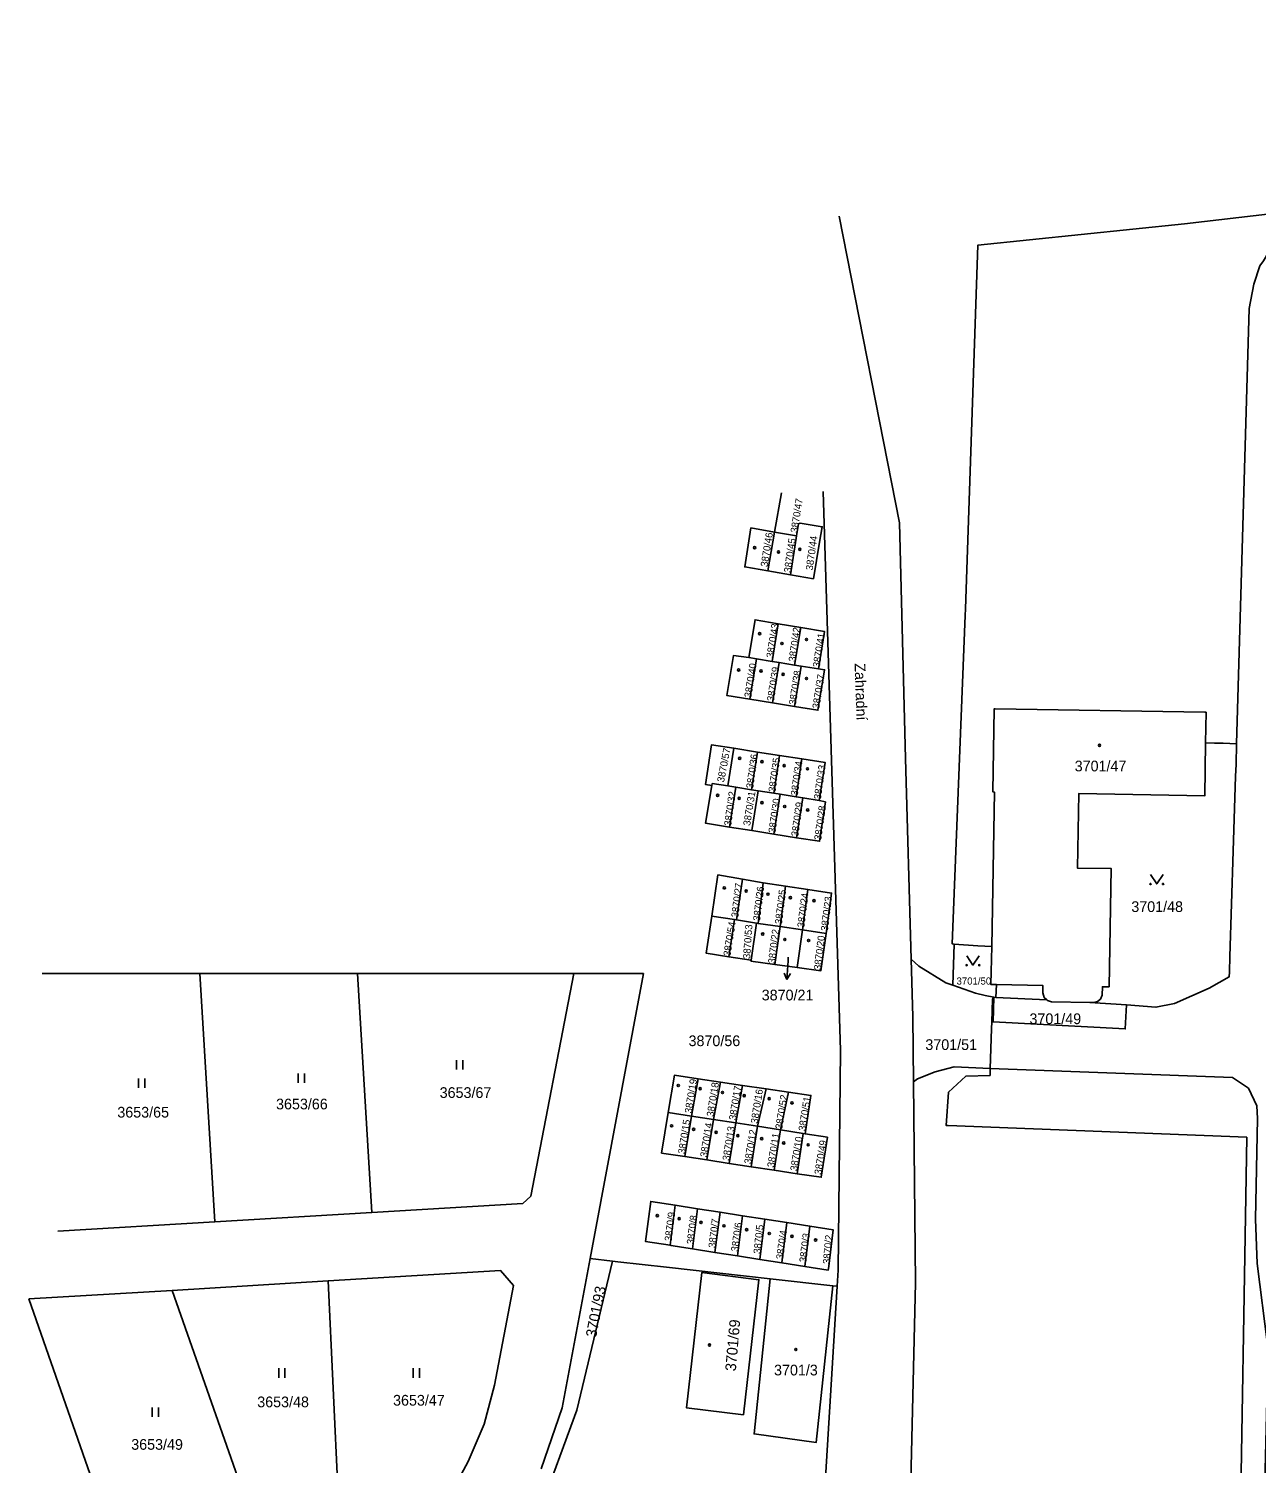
# Model space of a CAD drawing. Extents: x -527335 to -526256, y -1079142 to -1077809.
# Drawn here: x -527287.8 to -527092.7, y -1078063.8 to -1077835.8 of the extents above; entities that cross this region are included whole.
import ezdxf

# ---------------------------------------------------------------- set-up
doc = ezdxf.new("R2010")
doc.units = 0
for name, color, linetype in [('Vrstva 1', 7, 'Continuous'), ('Vrstva 2', 7, 'Continuous'), ('Vrstva 3', 7, 'Continuous'), ('Vrstva 4', 7, 'Continuous'), ('Vrstva 5', 7, 'Continuous'), ('Vrstva 7', 7, 'Continuous')]:
    doc.layers.add(name, color=color, linetype=linetype)

msp = doc.modelspace()

# ---------------------------------------------------------------- linework, layer by layer
at = {"layer": 'Vrstva 1'}
for p, q in [((-527168.2, -1077909.59), (-527169.28, -1077915.83)), ((-527169.28, -1077915.83), (-527173.06, -1077915.17)), ((-527169.28, -1077915.83), (-527170.35, -1077921.99)), ((-527165.79, -1077916.44), (-527169.28, -1077915.83)), ((-527170.35, -1077921.99), (-527166.78, -1077922.61)), ((-527168.69, -1077930.38), (-527169.69, -1077936.37)), ((-527165.12, -1077930.97), (-527168.69, -1077930.38)), ((-527165.12, -1077930.97), (-527166.12, -1077936.96)), ((-527172.16, -1077935.97), (-527173.38, -1077935.77)), ((-527172.16, -1077935.97), (-527173.2, -1077942.38)), ((-527169.69, -1077936.37), (-527172.16, -1077935.97)), ((-527168.57, -1077936.56), (-527169.69, -1077936.37)), ((-527168.57, -1077936.56), (-527169.61, -1077942.96)), ((-527166.12, -1077936.96), (-527168.57, -1077936.56)), ((-527165.08, -1077937.13), (-527166.12, -1077936.96)), ((-527165.08, -1077937.13), (-527166.12, -1077943.53)), ((-527162.33, -1077937.58), (-527165.08, -1077937.13)), ((-527173.2, -1077942.38), (-527169.61, -1077942.96)), ((-527169.61, -1077942.96), (-527166.12, -1077943.53)), ((-527175.75, -1077950.19), (-527176.69, -1077956.16)), ((-527172, -1077950.78), (-527175.75, -1077950.19)), ((-527172, -1077950.78), (-527172.94, -1077956.76)), ((-527168.48, -1077951.33), (-527172, -1077950.78)), ((-527168.48, -1077951.33), (-527169.41, -1077957.33)), ((-527164.93, -1077951.88), (-527168.48, -1077951.33)), ((-527164.93, -1077951.88), (-527165.87, -1077957.9)), ((-527175.46, -1077956.36), (-527176.69, -1077956.16)), ((-527175.46, -1077956.36), (-527176.46, -1077962.7)), ((-527172.94, -1077956.76), (-527175.46, -1077956.36)), ((-527171.91, -1077956.93), (-527172.94, -1077956.76)), ((-527171.91, -1077956.93), (-527172.91, -1077963.26)), ((-527169.41, -1077957.33), (-527171.91, -1077956.93)), ((-527168.41, -1077957.49), (-527169.41, -1077957.33)), ((-527168.41, -1077957.49), (-527169.41, -1077963.82)), ((-527165.87, -1077957.9), (-527168.41, -1077957.49)), ((-527164.78, -1077958.07), (-527165.87, -1077957.9)), ((-527164.78, -1077958.07), (-527165.78, -1077964.39)), ((-527162.18, -1077958.49), (-527164.78, -1077958.07)), ((-527176.46, -1077962.7), (-527172.91, -1077963.26)), ((-527172.91, -1077963.26), (-527169.41, -1077963.82)), ((-527169.41, -1077963.82), (-527165.78, -1077964.39)), ((-527174.41, -1077971), (-527175.35, -1077977.47)), ((-527171.1, -1077971.58), (-527174.41, -1077971)), ((-527171.1, -1077971.58), (-527171.88, -1077978.01)), ((-527167.53, -1077972.11), (-527171.1, -1077971.58)), ((-527167.53, -1077972.11), (-527168.41, -1077978.53)), ((-527163.98, -1077972.63), (-527167.53, -1077972.11)), ((-527163.98, -1077972.63), (-527164.85, -1077979.06)), ((-527179.26, -1077976.86), (-527175.68, -1077977.42)), ((-527175.68, -1077977.42), (-527176.58, -1077983.31)), ((-527175.68, -1077977.42), (-527175.35, -1077977.47)), ((-527175.35, -1077977.47), (-527172.18, -1077977.97)), ((-527172.18, -1077977.97), (-527173.01, -1077983.85)), ((-527171.88, -1077978.01), (-527172.18, -1077977.97)), ((-527168.41, -1077978.53), (-527171.88, -1077978.01)), ((-527168.41, -1077978.53), (-527169.23, -1077984.55)), ((-527164.85, -1077979.06), (-527168.41, -1077978.53)), ((-527164.85, -1077979.06), (-527165.67, -1077985.04)), ((-527161.11, -1077979.61), (-527164.85, -1077979.06)), ((-527140.94, -1077987.84), (-527140.72, -1077981.29)), ((-527176.58, -1077983.31), (-527173.01, -1077983.85)), ((-527285.69, -1077985.99), (-527260.64, -1077985.98)), ((-527260.64, -1077985.98), (-527235.6, -1077985.97)), ((-527258.27, -1078025.45), (-527260.64, -1077985.98)), ((-527235.6, -1077985.97), (-527201.2, -1077985.95)), ((-527233.32, -1078023.96), (-527235.6, -1077985.97)), ((-527201.2, -1077985.95), (-527208.02, -1078021.38)), ((-527201.2, -1077985.95), (-527190.13, -1077985.95)), ((-527190.13, -1077985.95), (-527198.62, -1078031.28)), ((-527169.23, -1077984.55), (-527165.67, -1077985.04)), ((-527119.18, -1077990.58), (-527113.33, -1077990.97)), ((-527181.44, -1078002.7), (-527182.49, -1078008.63)), ((-527177.88, -1078003.23), (-527181.44, -1078002.7)), ((-527177.88, -1078003.23), (-527179, -1078009.17)), ((-527174.36, -1078003.75), (-527177.88, -1078003.23)), ((-527174.36, -1078003.75), (-527175.45, -1078009.72)), ((-527170.64, -1078004.32), (-527174.36, -1078003.75)), ((-527172, -1078010.26), (-527170.64, -1078004.32)), ((-527167.08, -1078004.82), (-527170.64, -1078004.32)), ((-527167.08, -1078004.82), (-527168.36, -1078010.83)), ((-527182.49, -1078008.63), (-527186.19, -1078008.06)), ((-527182.49, -1078008.63), (-527183.55, -1078015.08)), ((-527179, -1078009.17), (-527182.49, -1078008.63)), ((-527179, -1078009.17), (-527180.04, -1078015.61)), ((-527175.45, -1078009.72), (-527179, -1078009.17)), ((-527175.45, -1078009.72), (-527176.48, -1078016.15)), ((-527172, -1078010.26), (-527175.45, -1078009.72)), ((-527172, -1078010.26), (-527173.03, -1078016.68)), ((-527168.36, -1078010.83), (-527172, -1078010.26)), ((-527168.36, -1078010.83), (-527169.37, -1078017.23)), ((-527164.72, -1078011.39), (-527168.36, -1078010.83)), ((-527165.72, -1078017.79), (-527164.72, -1078011.39)), ((-527164.4, -1078011.44), (-527164.72, -1078011.39)), ((-527183.55, -1078015.08), (-527180.04, -1078015.61)), ((-527180.04, -1078015.61), (-527176.48, -1078016.15)), ((-527176.48, -1078016.15), (-527173.03, -1078016.68)), ((-527173.03, -1078016.68), (-527169.37, -1078017.23)), ((-527169.37, -1078017.23), (-527165.72, -1078017.79)), ((-527233.32, -1078023.96), (-527258.27, -1078025.45)), ((-527185.08, -1078022.81), (-527185.88, -1078029.17)), ((-527181.52, -1078023.36), (-527185.08, -1078022.81)), ((-527181.52, -1078023.36), (-527182.33, -1078029.74)), ((-527177.96, -1078023.92), (-527181.52, -1078023.36)), ((-527177.96, -1078023.92), (-527178.77, -1078030.3)), ((-527174.39, -1078024.47), (-527177.96, -1078023.92)), ((-527174.39, -1078024.47), (-527175.2, -1078030.87)), ((-527170.84, -1078025.02), (-527174.39, -1078024.47)), ((-527170.84, -1078025.02), (-527171.65, -1078031.43)), ((-527167.33, -1078025.57), (-527170.84, -1078025.02)), ((-527258.27, -1078025.45), (-527283.23, -1078026.95)), ((-527167.33, -1078025.57), (-527168.15, -1078031.98)), ((-527163.67, -1078026.14), (-527167.33, -1078025.57)), ((-527163.67, -1078026.14), (-527164.48, -1078032.56)), ((-527198.62, -1078031.28), (-527195.06, -1078031.68)), ((-527182.33, -1078029.74), (-527178.77, -1078030.3)), ((-527178.77, -1078030.3), (-527175.2, -1078030.87)), ((-527175.2, -1078030.87), (-527171.65, -1078031.43)), ((-527171.65, -1078031.43), (-527168.15, -1078031.98)), ((-527168.15, -1078031.98), (-527164.48, -1078032.56)), ((-527287.85, -1078037.7), (-527265.02, -1078036.33)), ((-527265.02, -1078036.33), (-527240.25, -1078034.84)), ((-527265.02, -1078036.33), (-527249.76, -1078079.88)), ((-527240.25, -1078034.84), (-527238.34, -1078075.88)), ((-527160.02, -1078035.61), (-527169.98, -1078034.5)), ((-527159.33, -1078035.65), (-527160.02, -1078035.61)), ((-527287.85, -1078037.7), (-527270.53, -1078087.15))]:
    msp.add_line(p, q, dxfattribs=at)
for points in [[(-527140.72, -1077981.29), (-527141.06, -1077981.26), (-527138.97, -1077929.07), (-527138.93, -1077928.01), (-527137, -1077870.25), (-527104.11, -1077866.84), (-527021.38, -1077857.18), (-526949.01, -1077848.73), (-526843.67, -1077835.82)], [(-527095.85, -1077949.48), (-527093.83, -1077880.31), (-527093.1, -1077876.42), (-527092.14, -1077873.52), (-527091.56, -1077872.71), (-527090.02, -1077870.13), (-527087.99, -1077867.99), (-527085.4, -1077866.41), (-527080.52, -1077865.39), (-527007.85, -1077858.12), (-527005.84, -1077858.19), (-527004.97, -1077858.67), (-527002.17, -1077860.18), (-526999.36, -1077862.55), (-526998.01, -1077864.28), (-526997.69, -1077865.73), (-526997.86, -1077871.23)], [(-527147.58, -1077983.71), (-527148.5, -1077951.81), (-527149.41, -1077914.37), (-527159.03, -1077865.64)], [(-527161.57, -1077909.37), (-527158.79, -1077998.21), (-527159.18, -1078033.14), (-527159.33, -1078035.65)], [(-527173.06, -1077915.17), (-527174.03, -1077921.36), (-527170.35, -1077921.99)], [(-527166.78, -1077922.61), (-527163.1, -1077923.24), (-527162.13, -1077917.42), (-527161.72, -1077914.97), (-527165.2, -1077914.39)], [(-527165.2, -1077914.39), (-527165.48, -1077914.49), (-527165.79, -1077916.44)], [(-527165.79, -1077916.44), (-527165.85, -1077916.79), (-527166.78, -1077922.61)], [(-527168.69, -1077930.38), (-527172.38, -1077929.76), (-527173.38, -1077935.77)], [(-527162.33, -1077937.58), (-527161.37, -1077931.6), (-527165.12, -1077930.97)], [(-527173.38, -1077935.77), (-527175.8, -1077935.42), (-527176.88, -1077941.78), (-527173.2, -1077942.38)], [(-527166.12, -1077943.53), (-527162.39, -1077944.13), (-527161.35, -1077937.71), (-527162.33, -1077937.58)], [(-527134.77, -1077981.69), (-527134.33, -1077957.14), (-527134.59, -1077957.12), (-527134.36, -1077943.9), (-527134.2, -1077943.9), (-527100.92, -1077944.46), (-527100.7, -1077944.46), (-527100.77, -1077949.3)], [(-527179.25, -1077956.09), (-527180.29, -1077955.93), (-527179.29, -1077949.62), (-527175.75, -1077950.19)], [(-527119.18, -1077990.58), (-527118.6, -1077990.59), (-527117.95, -1077990.44), (-527117.46, -1077990.03), (-527117.21, -1077989.41), (-527117.18, -1077988.07), (-527116.12, -1077988.08), (-527115.76, -1077969.29), (-527121.12, -1077969.24), (-527120.93, -1077957.39), (-527100.9, -1077957.75), (-527100.77, -1077949.3)], [(-527095.85, -1077949.48), (-527095.91, -1077952.75), (-527096.01, -1077954.59), (-527096.41, -1077966.53), (-527096.91, -1077983.27), (-527096.98, -1077985.7), (-527097.03, -1077986.51), (-527100.23, -1077988.31), (-527105.72, -1077990.75), (-527108.68, -1077991.35), (-527113.33, -1077990.97)], [(-527100.77, -1077949.3), (-527099.35, -1077949.35), (-527097.98, -1077949.39), (-527095.85, -1077949.48)], [(-527162.18, -1077958.49), (-527161.24, -1077952.46), (-527164.93, -1077951.88)], [(-527179.25, -1077956.09), (-527180.24, -1077962.1), (-527176.46, -1077962.7)], [(-527176.69, -1077956.16), (-527179.2, -1077955.79), (-527179.25, -1077956.09)], [(-527165.78, -1077964.39), (-527162.13, -1077964.97), (-527161.21, -1077958.7), (-527162.18, -1077958.49)], [(-527174.41, -1077971), (-527178.3, -1077970.31), (-527179.26, -1077976.86)], [(-527161.11, -1077979.61), (-527160.23, -1077973.19), (-527163.98, -1077972.63)], [(-527179.26, -1077976.86), (-527180.14, -1077982.77), (-527176.58, -1077983.31)], [(-527165.67, -1077985.04), (-527161.93, -1077985.54), (-527161.11, -1077979.61)], [(-527140.72, -1077981.29), (-527137, -1077981.57), (-527134.77, -1077981.69)], [(-527134.77, -1077981.69), (-527134.89, -1077987.73), (-527134.03, -1077987.75)], [(-527173.01, -1077983.85), (-527173.04, -1077984.04), (-527169.23, -1077984.55)], [(-527147.58, -1077983.71), (-527146.35, -1077984.82), (-527142.07, -1077987.45), (-527140.94, -1077987.84)], [(-527147.21, -1078003.19), (-527147.31, -1077992.85), (-527147.58, -1077983.71)], [(-527140.94, -1077987.84), (-527137.35, -1077989.08), (-527135.82, -1077989.47), (-527134.43, -1077989.76)], [(-527134.03, -1077987.75), (-527134.13, -1077989.77), (-527134.43, -1077989.76)], [(-527134.03, -1077987.75), (-527126.63, -1077987.9), (-527126.65, -1077989.07), (-527126.44, -1077989.79), (-527126.03, -1077990.18), (-527125.92, -1077990.28), (-527125.26, -1077990.48), (-527119.18, -1077990.58)], [(-527134.43, -1077989.76), (-527134.66, -1077990.04), (-527134.76, -1077993.65), (-527134.79, -1077994.78), (-527135, -1078001.05)], [(-527113.33, -1077990.97), (-527113.55, -1077994.78), (-527134.55, -1077993.66), (-527134.43, -1077989.76)], [(-527181.44, -1078002.7), (-527185.21, -1078002.14), (-527186.19, -1078008.06)], [(-527147.21, -1078003.19), (-527146.56, -1078002.73), (-527143.75, -1078001.6), (-527140.75, -1078000.83), (-527135, -1078001.05)], [(-527135, -1078001.05), (-527135.04, -1078002.18), (-527138.91, -1078002.31), (-527141.63, -1078004.83), (-527142.01, -1078010.14), (-527141.69, -1078010.15), (-527094.23, -1078012.01), (-527095.45, -1078084.25), (-527022.3, -1078086.11), (-527016.88, -1078088.83)], [(-527015.84, -1078035.65), (-527015.24, -1078041.58), (-527017.7, -1078076.04), (-527091.49, -1078073.63), (-527090.95, -1078049.51), (-527090.94, -1078045), (-527092.6, -1078032.05), (-527092.82, -1078025.03), (-527092.53, -1078009.03), (-527092.64, -1078007.02), (-527093.93, -1078004.22), (-527096.47, -1078002.52), (-527135, -1078001.05)], [(-527151.32, -1078203.19), (-527149.15, -1078119.04), (-527147.89, -1078077.9), (-527146.9, -1078035.16), (-527147.21, -1078003.19)], [(-527164.4, -1078011.44), (-527163.51, -1078005.35), (-527167.08, -1078004.82)], [(-527186.19, -1078008.06), (-527187.25, -1078014.51), (-527183.55, -1078015.08)], [(-527165.72, -1078017.79), (-527161.87, -1078018.37), (-527160.88, -1078011.99), (-527164.4, -1078011.44)], [(-527208.02, -1078021.38), (-527209.32, -1078022.52), (-527233.32, -1078023.96)], [(-527185.08, -1078022.81), (-527188.98, -1078022.2), (-527189.82, -1078028.55), (-527185.88, -1078029.17)], [(-527164.48, -1078032.56), (-527160.77, -1078033.15), (-527160.74, -1078032.91), (-527159.95, -1078026.72), (-527163.67, -1078026.14)], [(-527185.88, -1078029.17), (-527185.7, -1078029.2), (-527184.06, -1078029.46), (-527182.33, -1078029.74)], [(-527195.06, -1078031.68), (-527200.73, -1078055.36), (-527206.71, -1078071.69), (-527212.24, -1078081.56)], [(-527198.62, -1078031.28), (-527203.07, -1078055.03), (-527206.41, -1078064.7)], [(-527169.98, -1078034.5), (-527186.45, -1078032.65), (-527194.19, -1078031.78), (-527195.06, -1078031.68)], [(-527240.25, -1078034.84), (-527212.84, -1078033.2), (-527210.76, -1078035.57), (-527213.81, -1078051.42), (-527215.47, -1078057.62), (-527217.99, -1078063.51), (-527221.44, -1078069.96)], [(-527174.21, -1078056.09), (-527183.27, -1078055.01), (-527180.87, -1078033.51), (-527171.77, -1078034.65), (-527174.21, -1078056.09)], [(-527160.02, -1078035.61), (-527162.69, -1078060.52), (-527172.55, -1078059.14), (-527169.98, -1078034.5)], [(-527168.74, -1078213.47), (-527166.4, -1078148.92), (-527166.12, -1078143.69), (-527163.93, -1078111.36), (-527159.33, -1078035.65)]]:
    msp.add_lwpolyline(points, dxfattribs=at)
at = {"layer": 'Vrstva 3'}
for p, q in [((-527219.85, -1078001.23), (-527219.85, -1077999.73)), ((-527218.85, -1078001.23), (-527218.85, -1077999.73)), ((-527245, -1078003.35), (-527245, -1078001.85)), ((-527244, -1078003.35), (-527244, -1078001.85)), ((-527270.41, -1078004.15), (-527270.41, -1078002.65)), ((-527269.41, -1078004.15), (-527269.41, -1078002.65)), ((-527248.11, -1078050.21), (-527248.11, -1078048.71)), ((-527247.11, -1078050.21), (-527247.11, -1078048.71)), ((-527226.73, -1078050.21), (-527226.73, -1078048.71)), ((-527225.73, -1078050.21), (-527225.73, -1078048.71)), ((-527268.23, -1078056.43), (-527268.23, -1078054.93)), ((-527267.23, -1078056.43), (-527267.23, -1078054.93))]:
    msp.add_line(p, q, dxfattribs=at)
for points in [[(-527109.53, -1077970.25), (-527108.53, -1077971.75), (-527107.53, -1077970.25)], [(-527138.75, -1077983.15), (-527137.75, -1077984.65), (-527136.75, -1077983.15)]]:
    msp.add_lwpolyline(points, dxfattribs=at)
for centre in [(-527109.53, -1077971.75), (-527107.53, -1077971.75), (-527138.75, -1077984.65), (-527136.75, -1077984.65)]:
    msp.add_circle(centre, 0.1, dxfattribs=at)
at = {"layer": 'Vrstva 4'}
for p, q in [((-527126.03, -1077990.18), (-527134.13, -1077989.77)), ((-527134.55, -1077993.66), (-527134.76, -1077993.65))]:
    msp.add_line(p, q, dxfattribs=at)
at = {"layer": 'Vrstva 5'}
for centre in [(-527172.46, -1077918.3), (-527168.66, -1077918.98), (-527165.27, -1077918.56), (-527171.66, -1077931.96), (-527168.11, -1077933.53), (-527164.21, -1077932.9), (-527175, -1077937.74), (-527171.43, -1077937.9), (-527167.93, -1077938.44), (-527164.21, -1077939.1), (-527117.64, -1077949.71), (-527174.83, -1077951.79), (-527171.29, -1077952.32), (-527167.76, -1077952.93), (-527164.06, -1077953.45), (-527178.34, -1077957.67), (-527174.92, -1077958.14), (-527171.3, -1077958.83), (-527167.67, -1077959.44), (-527164.02, -1077959.99), (-527177.28, -1077972.37), (-527173.8, -1077972.88), (-527170.33, -1077973.36), (-527166.77, -1077973.93), (-527163.02, -1077974.4), (-527171.17, -1077979.71), (-527167.65, -1077980.57), (-527163.87, -1077980.74), (-527184.6, -1078003.77), (-527181.11, -1078004.29), (-527177.57, -1078004.89), (-527174.11, -1078005.4), (-527170.14, -1078005.88), (-527166.51, -1078006.54), (-527185.66, -1078010.18), (-527182.15, -1078010.75), (-527178.58, -1078011.21), (-527175.13, -1078011.76), (-527171.33, -1078012.22), (-527167.83, -1078012.91), (-527163.94, -1078013.21), (-527187.93, -1078024.45), (-527184.45, -1078024.94), (-527180.98, -1078025.54), (-527177.33, -1078026.08), (-527173.73, -1078026.69), (-527170.13, -1078027.3), (-527166.53, -1078027.74), (-527162.77, -1078028.34), (-527179.63, -1078045.03), (-527165.9, -1078045.74)]:
    msp.add_circle(centre, 0.175, dxfattribs=at)
at = {"layer": 'Vrstva 7'}
for p, q in [((-527167.14, -1077983.96), (-527167.35, -1077986.95)), ((-527167.1, -1077983.4), (-527167.14, -1077983.96)), ((-527167.35, -1077986.95), (-527167.78, -1077985.92)), ((-527167.35, -1077986.95), (-527166.78, -1077985.99))]:
    msp.add_line(p, q, dxfattribs=at)

# ---------------------------------------------------------------- texts
at = {"layer": 'Vrstva 2'}
for s, height, rotation, p in [('3870/47', 1.139, 81, (-527165.65, -1077916.01)), ('3870/46', 1.139, 81, (-527170.4, -1077921.42)), ('3870/45', 1.14, 82, (-527166.69, -1077922.34)), ('3870/44', 1.139, 82, (-527163.23, -1077921.97)), ('3870/43', 1.139, 81, (-527169.49, -1077935.89)), ('3870/42', 1.139, 82, (-527165.95, -1077936.49)), ('3870/41', 1.14, 81, (-527162.12, -1077937.41)), ('3870/40', 1.14, 81, (-527172.99, -1077942.21)), ('3870/39', 1.14, 81, (-527169.4, -1077942.79)), ('3870/38', 1.14, 81, (-527165.91, -1077943.36)), ('3870/37', 1.14, 81, (-527162.18, -1077943.96)), ('3870/57', 1.139, 79, (-527177.33, -1077955.66)), ('3870/36', 1.14, 82, (-527172.69, -1077956.64)), ('3870/35', 1.14, 82, (-527169.16, -1077957.21)), ('3870/34', 1.14, 82, (-527165.61, -1077957.78)), ('3870/33', 1.14, 82, (-527161.93, -1077958.37)), ('3870/32', 1.14, 82, (-527176.2, -1077962.58)), ('3870/31', 1.139, 81, (-527173.17, -1077962.56)), ('3870/30', 1.14, 82, (-527169.16, -1077963.7)), ('3870/29', 1.14, 82, (-527165.53, -1077964.27)), ('3870/28', 1.14, 82, (-527161.88, -1077964.85)), ('3870/27', 1.14, 83, (-527175.06, -1077977.14)), ('3870/26', 1.14, 83, (-527171.59, -1077977.68)), ('3870/25', 1.14, 83, (-527168.12, -1077978.2)), ('3870/24', 1.14, 83, (-527164.56, -1077978.73)), ('3870/23', 1.14, 83, (-527160.82, -1077979.28)), ('3870/54', 1.14, 81, (-527176.32, -1077983.28)), ('3870/53', 1.14, 86, (-527173.18, -1077983.71)), ('3870/22', 1.14, 83, (-527169.21, -1077984.47)), ('3870/20', 1.14, 83, (-527161.94, -1077985.49)), ('3870/19', 1.14, 81, (-527182.47, -1078008.27)), ('3870/18', 1.14, 81, (-527178.98, -1078008.81)), ('3870/17', 1.14, 81, (-527175.43, -1078009.36)), ('3870/16', 1.14, 81, (-527171.98, -1078009.9)), ('3870/52', 1.14, 81, (-527168.07, -1078010.79)), ('3870/51', 1.14, 81, (-527164.38, -1078011.08)), ('3870/15', 1.14, 81, (-527183.53, -1078014.72)), ('3870/14', 1.14, 81, (-527180.02, -1078015.25)), ('3870/13', 1.14, 81, (-527176.46, -1078015.79)), ('3870/12', 1.14, 81, (-527173.01, -1078016.32)), ('3870/11', 1.14, 81, (-527169.35, -1078016.87)), ('3870/10', 1.14, 81, (-527165.7, -1078017.43)), ('3870/49', 1.14, 81, (-527161.85, -1078018.01)), ('3870/9', 1.14, 83, (-527185.65, -1078028.59)), ('3870/8', 1.14, 83, (-527182.14, -1078029.09)), ('3870/7', 1.14, 83, (-527178.69, -1078029.65)), ('3870/6', 1.14, 82, (-527175.1, -1078030.25)), ('3870/5', 1.139, 84, (-527171.53, -1078030.58)), ('3870/4', 1.14, 82, (-527167.94, -1078031.49)), ('3870/3', 1.14, 83, (-527164.24, -1078031.95)), ('3870/2', 1.139, 85, (-527160.49, -1078032.2)), ('3701/93', 1.7, 79, (-527197.66, -1078043.91)), ('3701/69', 1.7, 85, (-527175.45, -1078049.23))]:
    msp.add_text(s, height=height, rotation=rotation, dxfattribs=at).set_placement(p)
for s, height, p in [('3701/47', 1.7, (-527121.58, -1077953.85)), ('3701/48', 1.7, (-527112.58, -1077976.2)), ('3870/21', 1.7, (-527171.33, -1077990.25)), ('3701/50', 1.139, (-527140.36, -1077987.74)), ('3701/49', 1.7, (-527128.77, -1077994.02)), ('3870/56', 1.7, (-527182.96, -1077997.52)), ('3701/51', 1.7, (-527145.32, -1077998.13)), ('3653/67', 1.7, (-527222.52, -1078005.75)), ('3653/66', 1.7, (-527248.53, -1078007.57)), ('3653/65', 1.7, (-527273.76, -1078008.87)), ('3701/3', 1.7, (-527169.37, -1078049.85)), ('3653/48', 1.7, (-527251.52, -1078054.91)), ('3653/47', 1.7, (-527229.93, -1078054.65)), ('3653/49', 1.7, (-527271.55, -1078061.67))]:
    msp.add_text(s, height=height, dxfattribs=at).set_placement(p)
at = {"layer": 'Vrstva 7'}
msp.add_text('Zahradní', height=1.7, rotation=272, dxfattribs=at).set_placement((-527156.57, -1077936.69))

doc.saveas('drawing.dxf')
